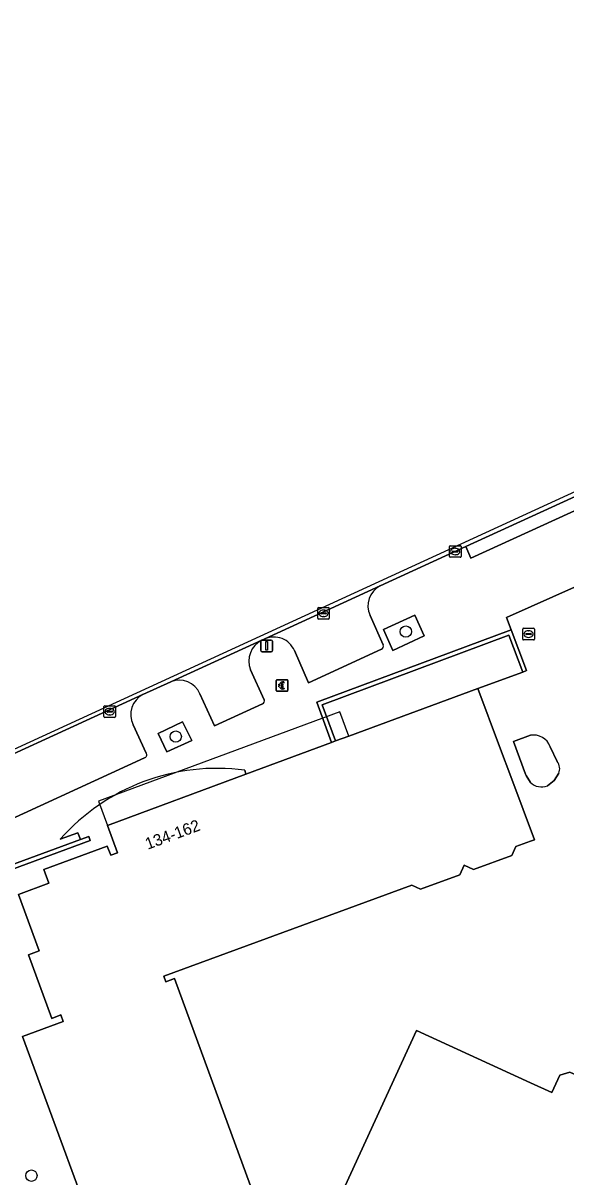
# Model space of a CAD drawing. Extents: x 160806 to 161707, y 383696 to 384148.
# Drawn here: x 160956.3 to 161003.1, y 383930 to 384029.3 of the extents above; entities that cross this region are included whole.
import ezdxf

# ---------------------------------------------------------------- set-up
doc = ezdxf.new("R2010")
doc.units = 0
for name, color, linetype in [('IMGEO_Betaalautomaat', 7, 'Continuous'), ('IMGEO_Boom', 7, 'Continuous'), ('IMGEO_Groenvoorziening', 7, 'Continuous'), ('IMGEO_Kolk', 7, 'Continuous'), ('IMGEO_Lichtmast', 7, 'Continuous'), ('IMGEO_Muur', 7, 'Continuous'), ('IMGEO_Pand', 7, 'Continuous'), ('IMGEO_Pand_nummerreeks', 7, 'Continuous'), ('IMGEO_Pand_overbouw', 7, 'Continuous'), ('IMGEO_Parkeervlak_open', 7, 'Continuous'), ('IMGEO_Rijbaan_lokaal_open', 7, 'Continuous'), ('IMGEO_Rioolput', 7, 'Continuous'), ('IMGEO_Terreindeel_gesloten', 7, 'Continuous'), ('IMGEO_Voetpad_open', 7, 'Continuous')]:
    doc.layers.add(name, color=color, linetype=linetype)

msp = doc.modelspace()

# ---------------------------------------------------------------- linework, layer by layer
at = {"layer": 'IMGEO_Betaalautomaat'}
for p, q in [((160978.127, 383971.872), (160978.127, 383972.713)), ((160978.127, 383972.713), (160978.127, 383971.872)), ((160978.202, 383972.796), (160979.043, 383972.796)), ((160979.043, 383972.796), (160978.202, 383972.796)), ((160978.41, 383972.26), (160978.41, 383972.328)), ((160978.531, 383972.328), (160978.531, 383972.26)), ((160978.789, 383972.601), (160978.772, 383972.501)), ((160978.776, 383972.095), (160978.798, 383972.008)), ((160979.126, 383972.722), (160979.126, 383971.881)), ((160979.126, 383971.881), (160979.126, 383972.722)), ((160979.052, 383971.797), (160978.211, 383971.797)), ((160978.211, 383971.797), (160979.052, 383971.797))]:
    msp.add_line(p, q, dxfattribs=at)
for points in [[(160978.41, 383972.328), (160978.341, 383972.328), (160978.341, 383972.397), (160978.42, 383972.397)], [(160978.415, 383972.191), (160978.341, 383972.191), (160978.341, 383972.26), (160978.41, 383972.26)], [(160978.542, 383972.397), (160978.689, 383972.397), (160978.689, 383972.328), (160978.531, 383972.328)], [(160978.531, 383972.26), (160978.689, 383972.26), (160978.689, 383972.191), (160978.545, 383972.191)]]:
    msp.add_lwpolyline(points, dxfattribs=at)
for centre, radius, start, end in [((160978.205, 383972.719), 0.0779, 92.4484, 184.28452), ((160978.205, 383972.719), 0.0779, 92.4484, 184.28452), ((160978.205, 383971.875), 0.0779, 182.4484, 274.28452), ((160978.205, 383971.875), 0.0779, 182.4484, 274.28452), ((160978.676, 383972.246), 0.267, 191.80956, 297.03891), ((160978.703, 383972.321), 0.293, 73.01398, 165.01395), ((160978.709, 383972.334), 0.179, 69.32359, 159.56827), ((160978.709, 383972.261), 0.179, 202.76249, 291.86925), ((160979.049, 383972.719), 0.0779, 2.4484, 94.28452), ((160979.049, 383972.719), 0.0779, 2.4484, 94.28452), ((160979.049, 383971.875), 0.0779, 272.4484, 4.28452), ((160979.049, 383971.875), 0.0779, 272.4484, 4.28452)]:
    msp.add_arc(centre, radius, start, end, dxfattribs=at)
at = {"layer": 'IMGEO_Boom'}
for centre in [(160989.277, 383976.933), (160969.47, 383967.898), (160957.047, 383930.124)]:
    msp.add_circle(centre, 0.489, dxfattribs=at)
at = {"layer": 'IMGEO_Groenvoorziening'}
for points in [[(160988.161, 383975.312), (160990.864, 383976.556), (160990.056, 383978.339), (160987.346, 383977.115)], [(160968.702, 383966.582), (160970.848, 383967.553), (160970.057, 383969.155), (160967.951, 383968.157)]]:
    msp.add_lwpolyline(points, close=True, dxfattribs=at)
at = {"layer": 'IMGEO_Kolk'}
for p, q in [((160993.03, 383983.397), (160993.03, 383984.249)), ((160993.105, 383984.323), (160993.957, 383984.323)), ((160993.289, 383983.817), (160993.289, 383983.829)), ((160993.727, 383983.78), (160993.329, 383983.78)), ((160993.332, 383983.866), (160993.73, 383983.866)), ((160993.518, 383984.103), (160993.543, 383984.103)), ((160993.773, 383983.829), (160993.773, 383983.817)), ((160994.031, 383984.249), (160994.031, 383983.397)), ((160993.957, 383983.323), (160993.105, 383983.323)), ((160993.541, 383983.543), (160993.516, 383983.543)), ((160981.689, 383978.076), (160981.689, 383978.928)), ((160981.764, 383979.002), (160982.616, 383979.002)), ((160982.177, 383978.782), (160982.202, 383978.782)), ((160982.69, 383978.928), (160982.69, 383978.076)), ((160982.616, 383978.002), (160981.764, 383978.002)), ((160981.948, 383978.496), (160981.948, 383978.508)), ((160982.386, 383978.459), (160981.988, 383978.459)), ((160981.991, 383978.545), (160982.389, 383978.545)), ((160982.2, 383978.222), (160982.175, 383978.222)), ((160982.432, 383978.508), (160982.432, 383978.496)), ((160963.287, 383969.623), (160963.287, 383970.475)), ((160963.362, 383970.549), (160964.214, 383970.549)), ((160963.546, 383970.043), (160963.546, 383970.055)), ((160963.984, 383970.006), (160963.586, 383970.006)), ((160963.589, 383970.092), (160963.987, 383970.092)), ((160963.775, 383970.329), (160963.8, 383970.329)), ((160964.03, 383970.055), (160964.03, 383970.043)), ((160964.288, 383970.475), (160964.288, 383969.623)), ((160964.214, 383969.549), (160963.362, 383969.549)), ((160963.798, 383969.769), (160963.773, 383969.769))]:
    msp.add_line(p, q, dxfattribs=at)
for points in [[(160993.03, 383983.397), (160993.03, 383984.249)], [(160993.105, 383984.323), (160993.957, 383984.323)], [(160994.031, 383984.249), (160994.031, 383983.397)], [(160993.957, 383983.323), (160993.105, 383983.323)], [(160981.689, 383978.076), (160981.689, 383978.928)], [(160981.764, 383979.002), (160982.616, 383979.002)], [(160982.69, 383978.928), (160982.69, 383978.076)], [(160982.616, 383978.002), (160981.764, 383978.002)], [(160963.287, 383969.623), (160963.287, 383970.475)], [(160963.362, 383970.549), (160964.214, 383970.549)], [(160964.288, 383970.475), (160964.288, 383969.623)], [(160964.214, 383969.549), (160963.362, 383969.549)]]:
    msp.add_lwpolyline(points, dxfattribs=at)
for centre, radius, start, end in [((160993.107, 383984.247), 0.0765, 91.55205, 178.44795), ((160993.107, 383984.247), 0.0765, 91.55205, 178.44795), ((160993.329, 383983.826), 0.0403, 85.87752, 175.75265), ((160993.326, 383983.816), 0.0366, 178.93798, 274.71019), ((160993.73, 383983.823), 0.043, 264.86636, 352.45326), ((160993.734, 383983.828), 0.0386, 1.73085, 96.63898), ((160993.955, 383984.247), 0.0765, 1.55205, 88.44795), ((160993.955, 383984.247), 0.0765, 1.55205, 88.44795), ((160993.107, 383983.399), 0.0765, 181.55205, 268.44795), ((160993.107, 383983.399), 0.0765, 181.55205, 268.44795), ((160993.955, 383983.399), 0.0765, 271.55205, 358.44795), ((160993.955, 383983.399), 0.0765, 271.55205, 358.44795), ((160981.766, 383978.926), 0.0765, 91.55205, 178.44795), ((160981.766, 383978.926), 0.0765, 91.55205, 178.44795), ((160982.614, 383978.926), 0.0765, 1.55205, 88.44795), ((160982.614, 383978.926), 0.0765, 1.55205, 88.44795), ((160981.766, 383978.078), 0.0765, 181.55205, 268.44795), ((160981.766, 383978.078), 0.0765, 181.55205, 268.44795), ((160981.988, 383978.505), 0.0403, 85.87752, 175.75265), ((160981.985, 383978.495), 0.0366, 178.93798, 274.71019), ((160982.389, 383978.502), 0.043, 264.86636, 352.45326), ((160982.393, 383978.507), 0.0386, 1.73085, 96.63898), ((160982.614, 383978.078), 0.0765, 271.55205, 358.44795), ((160982.614, 383978.078), 0.0765, 271.55205, 358.44795), ((160963.364, 383970.473), 0.0765, 91.55205, 178.44795), ((160963.364, 383970.473), 0.0765, 91.55205, 178.44795), ((160963.586, 383970.052), 0.0403, 85.87752, 175.75265), ((160963.583, 383970.042), 0.0366, 178.93798, 274.71019), ((160963.987, 383970.049), 0.043, 264.86636, 352.45326), ((160963.991, 383970.054), 0.0386, 1.73085, 96.63898), ((160964.212, 383970.473), 0.0765, 1.55205, 88.44795), ((160964.212, 383970.473), 0.0765, 1.55205, 88.44795), ((160963.364, 383969.625), 0.0765, 181.55205, 268.44795), ((160963.364, 383969.625), 0.0765, 181.55205, 268.44795), ((160964.212, 383969.625), 0.0765, 271.55205, 358.44795), ((160964.212, 383969.625), 0.0765, 271.55205, 358.44795)]:
    msp.add_arc(centre, radius, start, end, dxfattribs=at)
for centre, major_axis, ratio, start_param, end_param in [((160993.517, 383983.823), (-0.387, 0.002), 0.722429, 4.712389, 7.853982), ((160993.542, 383983.823), (-0.39, 0.002), 0.717154, 1.570796, 4.712389), ((160982.176, 383978.502), (-0.387, 0.002), 0.722429, 4.712389, 7.853982), ((160982.201, 383978.502), (-0.39, 0.002), 0.717154, 1.570796, 4.712389), ((160963.774, 383970.049), (-0.387, 0.002), 0.722429, 4.712389, 7.853982), ((160963.799, 383970.049), (-0.39, 0.002), 0.717154, 1.570796, 4.712389)]:
    msp.add_ellipse(centre, major_axis=major_axis, ratio=ratio, start_param=start_param, end_param=end_param, dxfattribs=at)
at = {"layer": 'IMGEO_Lichtmast'}
for p, q in [((160976.805, 383975.298), (160976.805, 383976.098)), ((160976.805, 383976.098), (160976.805, 383975.298)), ((160976.905, 383976.198), (160977.695, 383976.198)), ((160977.695, 383976.198), (160976.905, 383976.198)), ((160977.795, 383976.098), (160977.795, 383975.298)), ((160977.795, 383975.298), (160977.795, 383976.098)), ((160977.695, 383975.198), (160976.905, 383975.198)), ((160976.905, 383975.198), (160977.695, 383975.198))]:
    msp.add_line(p, q, dxfattribs=at)
msp.add_lwpolyline([(160977.225, 383976.073), (160977.375, 383976.073), (160977.375, 383975.323), (160977.225, 383975.323), (160977.225, 383976.073)], dxfattribs=at)
for centre, start, end in [((160976.905, 383976.098), 90, 180), ((160976.905, 383976.098), 90, 180), ((160977.695, 383976.098), 0, 90), ((160977.695, 383976.098), 360, 90), ((160976.905, 383975.298), 180, 270), ((160976.905, 383975.298), 180, 270), ((160977.695, 383975.298), 270, 0), ((160977.695, 383975.298), 270, 0)]:
    msp.add_arc(centre, 0.1, start, end, dxfattribs=at)
at = {"layer": 'IMGEO_Muur'}
for points in [[(160983.228, 383967.523), (160982.085, 383970.645), (160998.143, 383976.615), (160999.337, 383973.451), (160999.676, 383973.574), (160998.353, 383977.077), (160981.624, 383970.857), (160982.89, 383967.398)], [(160951.608, 383945.945), (160951.945, 383946.07), (160948.954, 383954.127), (160962.106, 383958.967), (160961.982, 383959.305), (160961.285, 383959.048), (160948.491, 383954.34)]]:
    msp.add_lwpolyline(points, close=True, dxfattribs=at)
at = {"layer": 'IMGEO_Pand'}
for points in [[(160977.173, 383925.8), (160969.36, 383947.074), (160968.633, 383946.807), (160968.457, 383947.286), (160989.798, 383955.124), (160990.551, 383954.776), (160993.927, 383956.015), (160994.304, 383956.829), (160995.097, 383956.462), (160998.389, 383957.671), (160998.749, 383958.448), (161000, 383958.902), (161000.341, 383959.026), (160998.393, 383964.227), (160997.341, 383967.036), (160995.462, 383972.051), (160984.364, 383967.944), (160983.228, 383967.523), (160982.89, 383967.398), (160975.504, 383964.664), (160963.59, 383960.254), (160964.46, 383957.905), (160963.873, 383957.689), (160963.583, 383958.479), (160958.126, 383956.475), (160958.56, 383955.294), (160955.925, 383954.326), (160957.713, 383949.459), (160956.787, 383949.119), (160958.794, 383943.656), (160959.589, 383943.948), (160959.797, 383943.383), (160956.293, 383942.096), (160964.049, 383920.98)], [(161000, 383968.013), (160998.549, 383967.48), (160999.583, 383964.664), (160999.621, 383964.561), (161000, 383963.955)], [(161002.304, 383965.748), (161001.707, 383967.03)], [(161001.466, 383963.653), (161002.049, 383964.116), (161002.444, 383964.746)], [(161006.3, 383909.334), (161016.1, 383930.706), (161004.448, 383936.067), (161005.121, 383937.543), (161004.802, 383938.387), (161003.399, 383939.03), (161002.526, 383938.756), (161001.835, 383937.27), (161000, 383938.112), (160990.19, 383942.611), (160980.975, 383922.577)]]:
    msp.add_lwpolyline(points, dxfattribs=at)
for centre, radius, start, end in [((161000.254, 383966.481), 1.553, 20.69742, 99.43039), ((161001.512, 383965.127), 1.007, 337.7883, 38.11952), ((161000.972, 383964.965), 1.402, 226.08831, 290.63119)]:
    msp.add_arc(centre, radius, start, end, dxfattribs=at)
at = {"layer": 'IMGEO_Pand_overbouw'}
msp.add_lwpolyline([(160963.59, 383960.254), (160975.504, 383964.664), (160982.89, 383967.398), (160983.228, 383967.523), (160984.364, 383967.944), (160983.592, 383970.029), (160962.818, 383962.339)], close=True, dxfattribs=at)
at = {"layer": 'IMGEO_Parkeervlak_open'}
for points in [[(160987.081, 383980.87), (160977.145, 383976.309)], [(160987.326, 383975.794), (160986.194, 383978.318)], [(160976.884, 383976.185), (160969.039, 383972.624)], [(160979.689, 383975.299), (160980.898, 383972.536), (160987.176, 383975.419)], [(160977.076, 383971.073), (160975.907, 383973.651)], [(160966.644, 383971.527), (160948.108, 383963.03)], [(160971.556, 383971.592), (160972.804, 383968.835), (160976.947, 383970.727)], [(160966.933, 383966.462), (160965.817, 383968.924)], [(160952.025, 383959.31), (160966.786, 383966.074)]]:
    msp.add_lwpolyline(points, dxfattribs=at)
for centre, radius, start, end in [((160987.931, 383979.144), 1.923, 116.21954, 205.44857), ((160977.763, 383974.391), 1.998, 116.103, 201.72807), ((160977.914, 383974.536), 1.932, 23.25023, 113.44237), ((160987.092, 383975.67), 0.265, 288.46796, 27.92923), ((160969.746, 383970.763), 1.991, 24.61384, 110.79773), ((160967.562, 383969.803), 1.954, 118.02313, 206.72569), ((160976.872, 383970.952), 0.237, 288.51929, 30.58655), ((160966.727, 383966.318), 0.251, 283.52504, 34.97497)]:
    msp.add_arc(centre, radius, start, end, dxfattribs=at)
at = {"layer": 'IMGEO_Rijbaan_lokaal_open'}
msp.add_lwpolyline([(160948.108, 383963.03), (160966.644, 383971.527), (160969.039, 383972.624), (160976.884, 383976.185), (160977.145, 383976.309), (160987.081, 383980.87), (160994.436, 383984.241), (161013.947, 383993.174), (161016.563, 383994.396), (161026.469, 383998.931), (161029.244, 384000.203), (161043.571, 384006.745), (161046.44, 384008.045), (161079.27, 384023.126), (161089.159, 384027.656), (161091.686, 384028.817), (161091.48, 384029.287), (161051.698, 384010.93), (161008.487, 383991.097), (160907.425, 383944.713)], dxfattribs=at)
at = {"layer": 'IMGEO_Rioolput'}
for p, q in [((160999.337, 383976.289), (160999.337, 383977.141)), ((160999.412, 383977.215), (161000.264, 383977.215)), ((160999.825, 383976.995), (160999.85, 383976.995)), ((161000.338, 383977.141), (161000.338, 383976.289)), ((161000.264, 383976.215), (160999.412, 383976.215)), ((160999.596, 383976.709), (160999.596, 383976.721)), ((161000.034, 383976.672), (160999.636, 383976.672)), ((160999.639, 383976.758), (161000.037, 383976.758)), ((160999.848, 383976.435), (160999.823, 383976.435)), ((161000.08, 383976.721), (161000.08, 383976.709))]:
    msp.add_line(p, q, dxfattribs=at)
for points in [[(160999.337, 383976.289), (160999.337, 383977.141)], [(160999.412, 383977.215), (161000.264, 383977.215)], [(161000.338, 383977.141), (161000.338, 383976.289)], [(161000.264, 383976.215), (160999.412, 383976.215)]]:
    msp.add_lwpolyline(points, dxfattribs=at)
for centre, radius, start, end in [((160999.414, 383977.139), 0.0765, 91.55205, 178.44795), ((160999.414, 383977.139), 0.0765, 91.55205, 178.44795), ((161000.262, 383977.139), 0.0765, 1.55205, 88.44795), ((161000.262, 383977.139), 0.0765, 1.55205, 88.44795), ((160999.414, 383976.291), 0.0765, 181.55205, 268.44795), ((160999.414, 383976.291), 0.0765, 181.55205, 268.44795), ((160999.636, 383976.718), 0.0403, 85.87752, 175.75265), ((160999.633, 383976.708), 0.0366, 178.93798, 274.71019), ((161000.037, 383976.715), 0.043, 264.86636, 352.45326), ((161000.041, 383976.72), 0.0386, 1.73085, 96.63898), ((161000.262, 383976.291), 0.0765, 271.55205, 358.44795), ((161000.262, 383976.291), 0.0765, 271.55205, 358.44795)]:
    msp.add_arc(centre, radius, start, end, dxfattribs=at)
for centre, major_axis, ratio, start_param, end_param in [((160999.824, 383976.715), (-0.387, 0.002), 0.722429, 4.712389, 7.853982), ((160999.849, 383976.715), (-0.39, 0.002), 0.717154, 1.570796, 4.712389)]:
    msp.add_ellipse(centre, major_axis=major_axis, ratio=ratio, start_param=start_param, end_param=end_param, dxfattribs=at)
at = {"layer": 'IMGEO_Terreindeel_gesloten'}
for points in [[(161005.888, 383976.146), (161004.053, 383980.875), (160997.944, 383978.148), (160998.353, 383977.077), (160999.676, 383973.574), (160999.337, 383973.451), (160995.462, 383972.051), (160997.341, 383967.036), (160998.393, 383964.227), (161000.341, 383959.026), (161000, 383958.902), (160998.749, 383958.448), (160998.389, 383957.671), (160995.097, 383956.462), (160994.304, 383956.829), (160993.927, 383956.015), (160990.551, 383954.776), (160989.798, 383955.124), (160968.457, 383947.286), (160968.633, 383946.807), (160969.36, 383947.074), (160977.173, 383925.8)], [(161000, 383963.955), (160999.621, 383964.561), (160999.583, 383964.664), (160998.549, 383967.48), (161000, 383968.013)], [(161001.707, 383967.03), (161002.304, 383965.748)], [(161002.444, 383964.746), (161002.049, 383964.116), (161001.466, 383963.653)], [(160980.975, 383922.577), (160990.19, 383942.611), (161000, 383938.112), (161001.835, 383937.27), (161002.526, 383938.756), (161003.399, 383939.03), (161004.802, 383938.387), (161005.121, 383937.543), (161004.448, 383936.067), (161016.1, 383930.706), (161006.3, 383909.334)]]:
    msp.add_lwpolyline(points, dxfattribs=at)
for centre, radius, start, end in [((161000.254, 383966.481), 1.553, 20.69742, 99.43039), ((161001.512, 383965.127), 1.007, 337.7883, 38.11952), ((161000.972, 383964.965), 1.402, 226.08831, 290.63119)]:
    msp.add_arc(centre, radius, start, end, dxfattribs=at)
at = {"layer": 'IMGEO_Voetpad_open'}
for points in [[(161016.563, 383994.396), (161013.947, 383993.174), (161014.397, 383992.177), (160994.873, 383983.238), (160994.436, 383984.241), (160987.081, 383980.87)], [(160975.411, 383965.01), (160975.504, 383964.664), (160982.89, 383967.398), (160981.624, 383970.857), (160998.353, 383977.077), (160997.944, 383978.148), (161004.053, 383980.875), (161009.792, 383983.427), (161016.05, 383986.21)], [(160986.194, 383978.318), (160987.326, 383975.794)], [(160977.145, 383976.309), (160976.884, 383976.185)], [(160987.176, 383975.419), (160980.898, 383972.536), (160979.689, 383975.299)], [(160975.907, 383973.651), (160977.076, 383971.073)], [(160969.039, 383972.624), (160966.644, 383971.527)], [(160976.947, 383970.727), (160972.804, 383968.835), (160971.556, 383971.592)], [(160965.817, 383968.924), (160966.933, 383966.462)], [(160966.786, 383966.074), (160952.025, 383959.31)], [(160964.049, 383920.98), (160956.293, 383942.096), (160959.797, 383943.383), (160959.589, 383943.948), (160958.794, 383943.656), (160956.787, 383949.119), (160957.713, 383949.459), (160955.925, 383954.326), (160958.56, 383955.294), (160958.126, 383956.475), (160963.583, 383958.479), (160963.873, 383957.689), (160964.46, 383957.905), (160963.59, 383960.254), (160975.504, 383964.664), (160975.411, 383965.01)], [(160930.868, 383948.143), (160928.691, 383946.466), (160915.435, 383936.839), (160917.241, 383931.994), (160917.656, 383932.175), (160917.798, 383931.792), (160919.628, 383932.473), (160919.501, 383932.83), (160920.227, 383933.101), (160919.857, 383934.55), (160919.885, 383935.916), (160932.177, 383945.058), (160934.167, 383946.323), (160938.381, 383949.591), (160940.209, 383950.755), (160941.963, 383951.859), (160947.428, 383954.476), (160947.637, 383954.018), (160948.491, 383954.34), (160961.285, 383959.048), (160961.058, 383959.607), (160959.525, 383959.063)], [(160959.525, 383959.063), (160961.058, 383959.607), (160961.285, 383959.048), (160961.982, 383959.305), (160962.106, 383958.967), (160948.954, 383954.127)]]:
    msp.add_lwpolyline(points, dxfattribs=at)
for points in [[(161013.947, 383993.174), (160994.436, 383984.241), (160994.873, 383983.238), (161014.397, 383992.177)], [(160990.864, 383976.556), (160988.161, 383975.312), (160987.346, 383977.115), (160990.056, 383978.339)], [(160995.462, 383972.051), (160999.337, 383973.451), (160998.143, 383976.615), (160982.085, 383970.645), (160983.228, 383967.523), (160984.364, 383967.944)], [(160970.848, 383967.553), (160968.702, 383966.582), (160967.951, 383968.157), (160970.057, 383969.155)]]:
    msp.add_lwpolyline(points, close=True, dxfattribs=at)
for centre, radius, start, end in [((160987.931, 383979.144), 1.923, 116.21954, 205.44857), ((160977.763, 383974.391), 1.998, 116.103, 201.72807), ((160977.914, 383974.536), 1.932, 23.25023, 113.44237), ((160987.092, 383975.67), 0.265, 288.46796, 27.92923), ((160969.746, 383970.763), 1.991, 24.61384, 110.79773), ((160967.562, 383969.803), 1.954, 118.02313, 206.72569), ((160976.872, 383970.952), 0.237, 288.51929, 30.58655), ((160966.727, 383966.318), 0.251, 283.52504, 34.97497), ((160973.041, 383947.151), 18.016, 82.43942, 138.60783), ((160973.041, 383947.151), 18.016, 82.43942, 138.60783)]:
    msp.add_arc(centre, radius, start, end, dxfattribs=at)

# ---------------------------------------------------------------- texts
at = {"layer": 'IMGEO_Pand_nummerreeks'}
msp.add_text('134-162', height=1, rotation=20.23114, dxfattribs=at).set_placement((160967.061, 383958.162))

doc.saveas('drawing.dxf')
